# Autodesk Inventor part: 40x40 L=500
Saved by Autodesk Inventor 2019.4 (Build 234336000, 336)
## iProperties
Created: 2020-04
Part Number: 40x40 L=500
Material: Generic
Document SubType Name: Modeling
Designer: Administrator
Density: 1 g/cm^3
Appearance: Default
Title: 40x40 L=500 v4
Author: Administrator
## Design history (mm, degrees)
feature "Body1"
body "Solid1"
